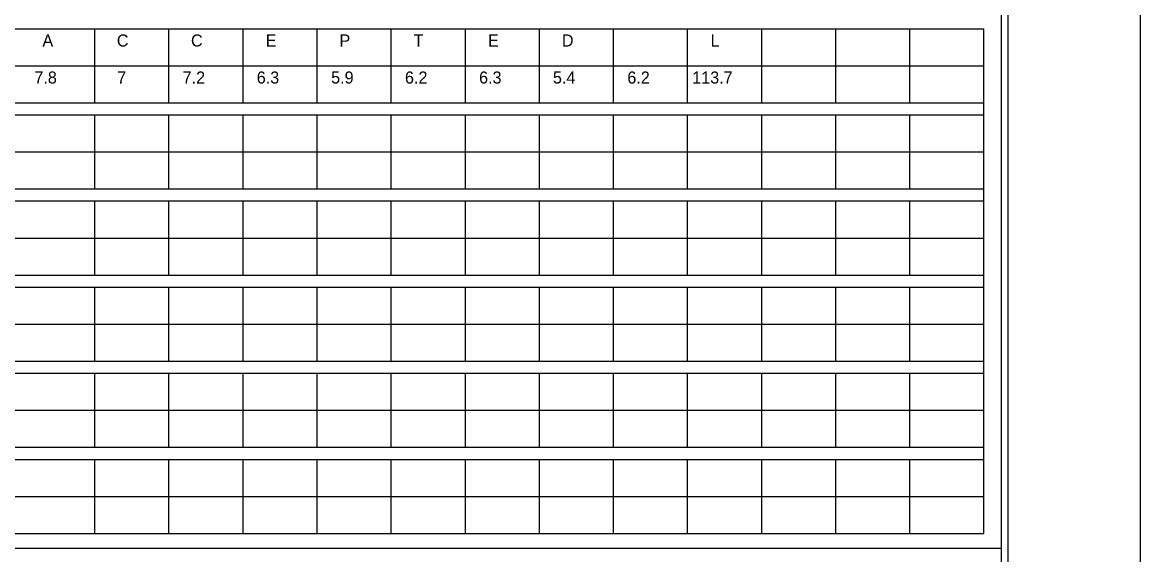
# Model space of a CAD drawing. Extents: x 17890628 to 17891459, y 17897314 to 17897992.
# Drawn here: x 17890794.41 to 17890830.75, y 17897458.18 to 17897475.46 of the extents above; entities that cross this region are included whole.
import ezdxf

# ---------------------------------------------------------------- set-up
doc = ezdxf.new("R2010")
doc.units = 0
for name, color, linetype in [('GSDims', 7, 'Continuous'), ('PlotBorder_dp', 7, 'Continuous'), ('SheetBorder_dp', 7, 'Continuous'), ('SheetLinesMisc2_dp', 7, 'Continuous')]:
    doc.layers.add(name, color=color, linetype=linetype)

msp = doc.modelspace()

# ---------------------------------------------------------------- linework, layer by layer
at = {"layer": 'PlotBorder_dp'}
msp.add_lwpolyline([(17890701.346, 17897413.687), (17890830.745, 17897413.687), (17890830.745, 17897496.818), (17890701.346, 17897496.818)], close=True, dxfattribs=at)
at = {"layer": 'SheetBorder_dp'}
msp.add_line((17890826.432, 17897496.034), (17890826.432, 17897414.472), dxfattribs=at)
at = {"layer": 'SheetLinesMisc2_dp'}
for p, q in [((17890826.223, 17897420.931), (17890826.223, 17897495.848)), ((17890766.458, 17897475.25), (17890825.647, 17897475.25)), ((17890796.754, 17897475.25), (17890796.754, 17897472.846)), ((17890799.162, 17897475.25), (17890799.162, 17897472.846)), ((17890801.57, 17897475.25), (17890801.57, 17897472.846)), ((17890803.977, 17897475.25), (17890803.977, 17897472.846)), ((17890806.385, 17897475.25), (17890806.385, 17897472.846)), ((17890808.793, 17897475.25), (17890808.793, 17897472.846)), ((17890811.201, 17897475.25), (17890811.201, 17897472.846)), ((17890813.608, 17897475.25), (17890813.608, 17897472.846)), ((17890816.016, 17897475.25), (17890816.016, 17897472.846)), ((17890818.424, 17897475.25), (17890818.424, 17897472.846)), ((17890820.832, 17897475.25), (17890820.832, 17897472.846)), ((17890823.239, 17897475.25), (17890823.239, 17897472.846)), ((17890825.647, 17897458.862), (17890825.647, 17897475.25)), ((17890766.458, 17897474.048), (17890825.647, 17897474.048)), ((17890766.458, 17897472.846), (17890825.647, 17897472.846)), ((17890766.458, 17897472.453), (17890825.647, 17897472.453)), ((17890796.754, 17897472.453), (17890796.754, 17897470.049)), ((17890799.162, 17897472.453), (17890799.162, 17897470.049)), ((17890801.57, 17897472.453), (17890801.57, 17897470.049)), ((17890803.977, 17897472.453), (17890803.977, 17897470.049)), ((17890806.385, 17897472.453), (17890806.385, 17897470.049)), ((17890808.793, 17897472.453), (17890808.793, 17897470.049)), ((17890811.201, 17897472.453), (17890811.201, 17897470.049)), ((17890813.608, 17897472.453), (17890813.608, 17897470.049)), ((17890816.016, 17897472.453), (17890816.016, 17897470.049)), ((17890818.424, 17897472.453), (17890818.424, 17897470.049)), ((17890820.832, 17897472.453), (17890820.832, 17897470.049)), ((17890823.239, 17897472.453), (17890823.239, 17897470.049)), ((17890766.458, 17897471.251), (17890825.647, 17897471.251)), ((17890766.458, 17897470.049), (17890825.647, 17897470.049)), ((17890766.458, 17897469.657), (17890825.647, 17897469.657)), ((17890796.754, 17897469.657), (17890796.754, 17897467.252)), ((17890799.162, 17897469.657), (17890799.162, 17897467.252)), ((17890801.57, 17897469.657), (17890801.57, 17897467.252)), ((17890803.977, 17897469.657), (17890803.977, 17897467.252)), ((17890806.385, 17897469.657), (17890806.385, 17897467.252)), ((17890808.793, 17897469.657), (17890808.793, 17897467.252)), ((17890811.201, 17897469.657), (17890811.201, 17897467.252)), ((17890813.608, 17897469.657), (17890813.608, 17897467.252)), ((17890816.016, 17897469.657), (17890816.016, 17897467.252)), ((17890818.424, 17897469.657), (17890818.424, 17897467.252)), ((17890820.832, 17897469.657), (17890820.832, 17897467.252)), ((17890823.239, 17897469.657), (17890823.239, 17897467.252)), ((17890766.458, 17897468.454), (17890825.647, 17897468.454)), ((17890766.458, 17897467.252), (17890825.647, 17897467.252)), ((17890766.458, 17897466.86), (17890825.647, 17897466.86)), ((17890796.754, 17897466.86), (17890796.754, 17897464.455)), ((17890799.162, 17897466.86), (17890799.162, 17897464.455)), ((17890801.57, 17897466.86), (17890801.57, 17897464.455)), ((17890803.977, 17897466.86), (17890803.977, 17897464.455)), ((17890806.385, 17897466.86), (17890806.385, 17897464.455)), ((17890808.793, 17897466.86), (17890808.793, 17897464.455)), ((17890811.201, 17897466.86), (17890811.201, 17897464.455)), ((17890813.608, 17897466.86), (17890813.608, 17897464.455)), ((17890816.016, 17897466.86), (17890816.016, 17897464.455)), ((17890818.424, 17897466.86), (17890818.424, 17897464.455)), ((17890820.832, 17897466.86), (17890820.832, 17897464.455)), ((17890823.239, 17897466.86), (17890823.239, 17897464.455)), ((17890766.458, 17897465.658), (17890825.647, 17897465.658)), ((17890766.458, 17897464.455), (17890825.647, 17897464.455)), ((17890766.458, 17897464.063), (17890825.647, 17897464.063)), ((17890796.754, 17897464.063), (17890796.754, 17897461.659)), ((17890799.162, 17897464.063), (17890799.162, 17897461.659)), ((17890801.57, 17897464.063), (17890801.57, 17897461.659)), ((17890803.977, 17897464.063), (17890803.977, 17897461.659)), ((17890806.385, 17897464.063), (17890806.385, 17897461.659)), ((17890808.793, 17897464.063), (17890808.793, 17897461.659)), ((17890811.201, 17897464.063), (17890811.201, 17897461.659)), ((17890813.608, 17897464.063), (17890813.608, 17897461.659)), ((17890816.016, 17897464.063), (17890816.016, 17897461.659)), ((17890818.424, 17897464.063), (17890818.424, 17897461.659)), ((17890820.832, 17897464.063), (17890820.832, 17897461.659)), ((17890823.239, 17897464.063), (17890823.239, 17897461.659)), ((17890766.458, 17897462.861), (17890825.647, 17897462.861)), ((17890766.458, 17897461.659), (17890825.647, 17897461.659)), ((17890766.458, 17897461.267), (17890825.647, 17897461.267)), ((17890796.754, 17897461.267), (17890796.754, 17897458.862)), ((17890799.162, 17897461.267), (17890799.162, 17897458.862)), ((17890801.57, 17897461.267), (17890801.57, 17897458.862)), ((17890803.977, 17897461.267), (17890803.977, 17897458.862)), ((17890806.385, 17897461.267), (17890806.385, 17897458.862)), ((17890808.793, 17897461.267), (17890808.793, 17897458.862)), ((17890811.201, 17897461.267), (17890811.201, 17897458.862)), ((17890813.608, 17897461.267), (17890813.608, 17897458.862)), ((17890816.016, 17897461.267), (17890816.016, 17897458.862)), ((17890818.424, 17897461.267), (17890818.424, 17897458.862)), ((17890820.832, 17897461.267), (17890820.832, 17897458.862)), ((17890823.239, 17897461.267), (17890823.239, 17897458.862)), ((17890766.458, 17897460.065), (17890825.647, 17897460.065)), ((17890766.458, 17897458.862), (17890825.647, 17897458.862)), ((17890705.872, 17897458.39), (17890826.223, 17897458.39))]:
    msp.add_line(p, q, dxfattribs=at)

# ---------------------------------------------------------------- texts
at = {"layer": 'GSDims'}
for s, height, p in [('A', 0.392, (17890795.062, 17897474.672)), ('C', 0.392, (17890797.479, 17897474.672)), ('C', 0.392, (17890799.888, 17897474.672)), ('E', 0.392, (17890802.315, 17897474.672)), ('P', 0.392, (17890804.714, 17897474.672)), ('T', 0.392, (17890807.122, 17897474.672)), ('E', 0.392, (17890809.54, 17897474.672)), ('D', 0.392, (17890811.939, 17897474.672)), ('L', 0.392, (17890816.774, 17897474.672)), ('7.8', 0.3921, (17890794.8, 17897473.47)), ('7', 0.392, (17890797.489, 17897473.47)), ('7.2', 0.3921, (17890799.617, 17897473.47)), ('6.3', 0.3921, (17890802.025, 17897473.47)), ('5.9', 0.3921, (17890804.443, 17897473.47)), ('6.2', 0.3921, (17890806.842, 17897473.47)), ('6.3', 0.3921, (17890809.25, 17897473.47)), ('5.4', 0.3921, (17890811.649, 17897473.47)), ('6.2', 0.3921, (17890814.067, 17897473.47)), ('113.7', 0.3921, (17890816.176, 17897473.47))]:
    msp.add_text(s, height=height, dxfattribs=at).set_placement(p)

doc.saveas('drawing.dxf')
